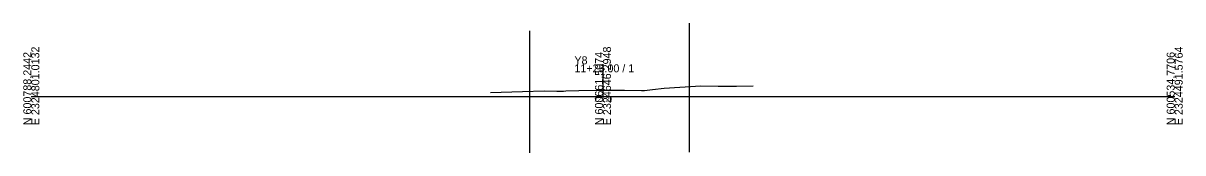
# Model space of a CAD drawing. Extents: x -26 to 2324730, y 979 to 600638.
# Drawn here: x 1397.2 to 1802.8, y 980.4 to 1025.6 of the extents above; entities that cross this region are included whole.
import ezdxf

# ---------------------------------------------------------------- set-up
doc = ezdxf.new("R2010")
doc.units = 0
for name, color, linetype in [('Exist Cross Section Cell', 7, 'Continuous'), ('Exist XS Center Line Elevation Label', 7, 'Continuous'), ('Exist XS Ground Line', 7, 'Continuous'), ('Prop XS Exc Vertical Line 1', 7, 'Continuous'), ('Prop XS Exc Vertical Line 4', 7, 'Continuous')]:
    doc.layers.add(name, color=color, linetype=linetype)

msp = doc.modelspace()

# ---------------------------------------------------------------- linework, layer by layer
at = {"layer": 'Exist Cross Section Cell'}
for p, q in [((1600, 1000), (1600, 1011.28)), ((1400, 1000), (1600, 1000)), ((1600, 1000), (1800, 1000))]:
    msp.add_line(p, q, dxfattribs=at)
at = {"layer": 'Exist XS Ground Line'}
msp.add_lwpolyline([(1560.6, 1001.38), (1571.79, 1001.82), (1579.44, 1002.01), (1583.84, 1001.95), (1585.75, 1001.95), (1586.18, 1001.93), (1586.98, 1002.04), (1591.53, 1002.14), (1597.78, 1002.23), (1600, 1002.23), (1603.86, 1002.23), (1607.5, 1002.21), (1613.45, 1002.18), (1614.47, 1002.18), (1617.29, 1002.53), (1621.43, 1002.92), (1634.19, 1003.72), (1640.34, 1003.6), (1646.65, 1003.7), (1652.48, 1003.76)], dxfattribs=at)
at = {"layer": 'Prop XS Exc Vertical Line 1'}
msp.add_line((1574.24, 1022.98), (1574.24, 980.38), dxfattribs=at)
at = {"layer": 'Prop XS Exc Vertical Line 4'}
msp.add_line((1630.12, 1025.63), (1630.12, 980.6), dxfattribs=at)

# ---------------------------------------------------------------- texts
at = {"layer": 'Exist Cross Section Cell'}
for s, p in [('N 600788.2442', (1400, 990)), ('E 2324801.0132', (1402.8, 990)), ('N 600661.5074', (1600, 990)), ('E 2324646.2948', (1602.8, 990)), ('N 600534.7706', (1800, 990)), ('E 2324491.5764', (1802.8, 990))]:
    msp.add_text(s, height=2.8, rotation=90, dxfattribs=at).set_placement(p)
for s, p in [('Y8', (1590, 1011.28)), ('11+25.00 / 1', (1590, 1008.48))]:
    msp.add_text(s, height=2.8, dxfattribs=at).set_placement(p)
at = {"layer": 'Exist XS Center Line Elevation Label'}
msp.add_text('122.23', height=1.5, dxfattribs=at).set_placement((1596.94, 998.23))

doc.saveas('drawing.dxf')
